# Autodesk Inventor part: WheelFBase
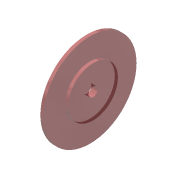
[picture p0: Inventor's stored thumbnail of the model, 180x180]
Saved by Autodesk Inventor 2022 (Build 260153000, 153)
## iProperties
Created: 2010-08
Part Number: WheelFBase
Document SubType Name: Modeling
Designer: nguyenducthang
Density: 1 g/cm^3
Mass: 111.723 g
Surface Area: 390.736 cm^2
Volume: 111.723 cm^3
Material: Generico
Appearance: Rosso scuro
Author: nguyenducthang
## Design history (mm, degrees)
revolve "Revolution7" stored, may be unused: angle "d462" = 90 deg
coil "Coil9" pitch "d536" = 16; turns "d538" = 3; dims "d537" = 10, "d539" = 0, angle "d540" = 90 deg, angle "d541" = 90 deg, "d542" = 0, "d543" = 0
sketch "Sketch81"
  geometry: C1 r 75 at (0, 0) reference; C2 r 7.5 at (0, 0)
  constraints: 1 centre point, 1 coincident
  dimensions: "d560" = 15 diameter of C2
extrude "Extrusion65" cut sketch "Sketch81" extent not by distance; stored distance "d561" = 10; taper "d562" = 0 deg
node "Solido1"
node "Corpi solidi"
node "Corpi di superficie"
sketch "Sketch69"
  geometry: L1 (0, 0)-(0, 75); L2 (0, 75)-(5, 75); L3 (5, 75)-(5, 40); L4 (5, 40)-(10, 40); L5 (10, 40)-(10, 0); L6 (72, 0)-(0, 0)
  constraints: 12 end point, 4 parallel, 1 perpendicular, 1 point on line, 1 vertical, 1 other
  dimensions: "d454" = 75 distance of L1.start L1.end; "d458" = 5 distance of L1.end L2.end; "d459" = 5 distance of L3.end L4.end; "d559" = 40 distance between parallel lines of L4 L6
sketch "Sketch78"
  geometry: L1 (0, 75)-(5, 75) reference; L2 (0, -75)-(0, 75) reference; L3 (0, 8)-(-12.2, 8); L4 (0, 12)-(0, 8); L5 (0, 0)-(-29.088, 0); L6 (-12.2, 8)-(-12.2, 12); L7 (-12.2, 12)-(0, 12)
  constraints: 10 end point, 2 perpendicular, 1 collinear, 1 midpoint, 1 point on line
  dimensions: "d556" = 8 distance between parallel lines of L3 L5; "d557" = 4 distance of L3.end L6.end; "d558" = 12.2 distance of L6.end L4.start
other parameters: "d489" = 6.19982 (derived)
